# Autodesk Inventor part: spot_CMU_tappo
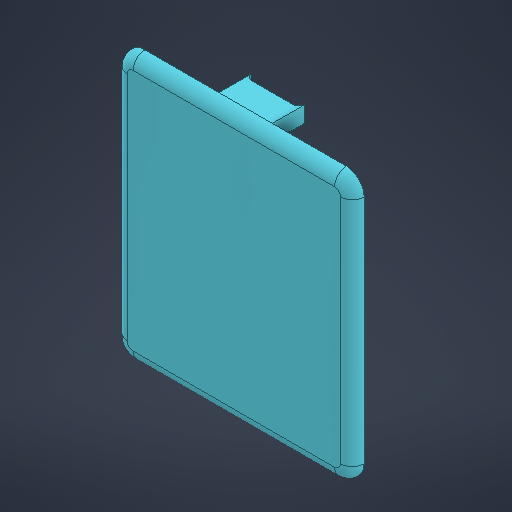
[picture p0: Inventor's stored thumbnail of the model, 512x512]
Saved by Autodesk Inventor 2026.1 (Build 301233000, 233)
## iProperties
Created: 2025-11
Part Number: spot_CMU_tappo
Material: Generico
Document SubType Name: Modeling
Designer: Gek
Density: 1 g/cm^3
Appearance: Verde turchese
Author: Gek
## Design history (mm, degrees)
sketch "Schizzo1"
  geometry: L1 (20, 22.5)-(-20, 22.5); L2 (-20, 22.5)-(-20, -22.5); L3 (-20, -22.5)-(20, -22.5); L4 (20, -22.5)-(20, 22.5); L5 (20, 22.5)-(-20, -22.5); L6 (-20, 22.5)-(20, -22.5); 1 further point
  constraints: 12 end point, 2 midpoint, 2 parallel, 1 horizontal, 1 perpendicular
  dimensions: "d0" = 45 distance of L3.end L1.start; "d1" = 40 distance of L2.end L3.end
extrude "Estrusione1" new body sketch "Schizzo1" distance "d2" = 2; taper "d3" = 0 deg
sketch "Schizzo2"
  geometry: L1 (-15.8, -19.8)-(15.8, -19.8); L2 (15.8, -19.8)-(15.8, 19.8); L3 (15.8, 19.8)-(-15.8, 19.8); L4 (-15.8, 19.8)-(-15.8, -19.8); L5 (-15.8, -19.8)-(15.8, 19.8); L6 (15.8, -19.8)-(-15.8, 19.8); 1 further point
  constraints: 12 end point, 2 midpoint, 2 parallel, 1 horizontal, 1 perpendicular
  dimensions: "d4" = 31.6 distance of L1.start L1.end; "d5" = 39.6 distance of L3.end L1.start
extrude "Estrusione2" join sketch "Schizzo2" distance "d6" = 1.5; taper "d7" = 0 deg
sketch "Schizzo3"
  geometry: L1 (-13.8, -17.8)-(13.8, -17.8); L2 (13.8, -17.8)-(13.8, 17.8); L3 (13.8, 17.8)-(-13.8, 17.8); L4 (-13.8, 17.8)-(-13.8, -17.8); L5 (-13.8, -17.8)-(13.8, 17.8); L6 (13.8, -17.8)-(-13.8, 17.8); L7 (-15.8, 19.8)-(-15.8, -19.8) reference; L8 (-15.8, -19.8)-(15.8, -19.8) reference; 1 further point
  constraints: 12 end point, 2 midpoint, 2 parallel, 1 horizontal, 1 perpendicular
  dimensions: "d8" = 2 distance between parallel lines of L4 L7; "d9" = 2 distance between parallel lines of L8 L1
extrude "Estrusione3" cut sketch "Schizzo3" stored distance "d10" = 2; taper "d11" = 0 deg
sketch "Schizzo4"
  geometry: L1 (-20, -22.5)-(20, -22.5) reference; L2 (-15.8, -19.8)-(15.8, -19.8) reference; L3 (4.5, -22.5)-(-4.5, -22.5); L4 (-4.5, -22.5)-(-4.5, -19.8); L5 (-4.5, -19.8)-(4.5, -19.8); L6 (4.5, -19.8)-(4.5, -22.5); L7 (0, 31.5)-(0, -31.5) reference; 3 further points
  constraints: 8 end point, 2 parallel, 2 point on line, 1 horizontal, 1 perpendicular, 1 other
  dimensions: "d12" = 9 distance between parallel lines of L4 L6
sketch "Schizzo5"
  geometry: 1 further point
extrude "Estrusione4" join sketch "Schizzo4" distance "d13" = 5.5; taper "d14" = 0 deg
fillet "Raccordo2" dims "d16" = 3
fillet "Raccordo3" dims "d17" = 2
sketch "Schizzo6"
  geometry: L1 (9, -4)-(9, 0) reference; L2 (9, 0)-(0, 0); L3 (8, -1)-(1, -1); L4 (1, 1)-(8, 1); L5 (0, 0)-(9, 0) reference; A1 r 1 centre (8, 0) between (8, -1) and (8, 1); A2 r 1 centre (1, 0) between (1, 1) and (1, -1); 4 further points
  constraints: 8 end point, 6 point on circle, 4 tangent, 3 point on line, 2 centre point, 1 collinear, 1 midpoint, 1 parallel, 1 perpendicular
  dimensions: "d18" = 2 distance between parallel lines of L4 L3
extrude "Estrusione5" cut sketch "Schizzo6" distance "d19" = 5.5; taper "d20" = 0 deg
node "Solido1"
